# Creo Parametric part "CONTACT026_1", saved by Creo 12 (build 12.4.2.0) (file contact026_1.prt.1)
Units: Custom; MM, KILOGRAM, SECS

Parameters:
  PTC_WM_ITERATION = "0"
  PTC_WM_VERSION = "-.0"
  PTC_WM_LIFECYCLE_STATE = "In Work"
  PTC_WM_LIFECYCLE = "MO_CADDocument"
  PTC_WM_CREATED_BY = "Maximilian Roepper (Z0017RMS: MO)"
  PTC_WM_CREATED_ON = "18-Sep-26 11:36:42 AM"
  PTC_WM_MODIFIED_BY = "Maximilian Roepper (Z0017RMS: MO)"
  PTC_WM_MODIFIED_ON = "18-Sep-26 11:36:46 AM"
  PDMLINKNUMBER = "PDM000071455141"
  PTC_WM_NAME = "contact026_1.prt"
  PTC_WM_NUMBER = "PDM000071455141"

Other parameters: WEIGHT, WEIGHT_FACTOR, WEIGHT_ADD, _MASS_TEMP, _DIFF_TEMP, MC_ERRORS, SUPPLIER

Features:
  1. coordinate system
  2. datum plane "PRT_YZ"
  3. datum plane "PRT_XY"
  4. datum plane "PRT_XZ"
  5. coordinate system
  6. datum axis
  7. datum axis
  8. datum axis
  9. coordinate system
  10. imported feature

Other named items: PRT, SIEMENS_MO, DRW_VIEW_ORG, PRT_X, PRT_Y, PRT_Z, CS0, ROUGH_GROB

Layers: 00_STD_CSYS-KSYS, 01_STD_PLANES-EBENEN, 02_STD_AXES-ACHSEN, 03_STD_CSYS-KSYS, 24_IMPORT_FEAT-IMPORT_KE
